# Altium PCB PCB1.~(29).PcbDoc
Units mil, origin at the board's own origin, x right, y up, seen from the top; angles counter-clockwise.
Board outline 5610 x 800 mil, 2 copper layers (Top Layer, Bottom Layer); 100 components, 175 nets, 474 pads, 134 vias.
Unrouted connection lines stored in the file: 2.
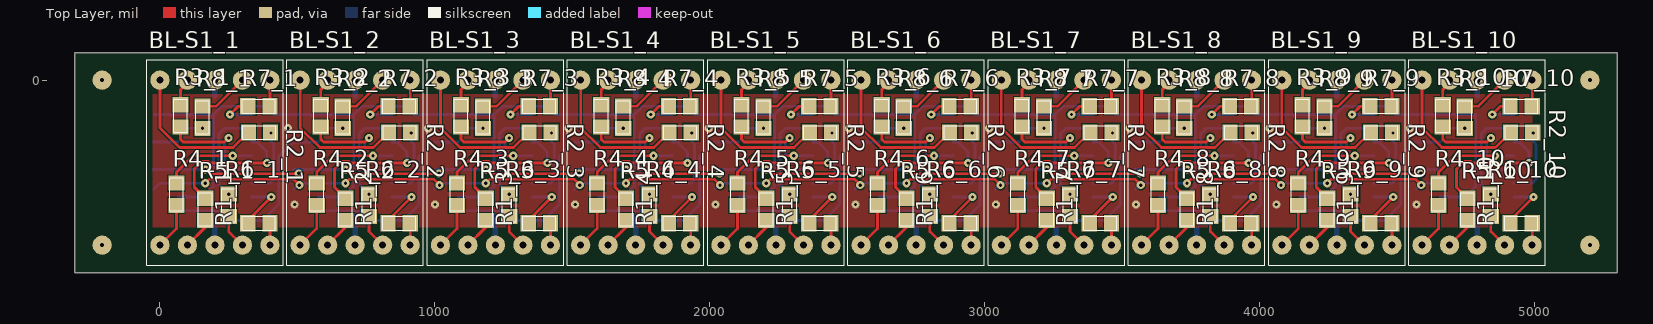
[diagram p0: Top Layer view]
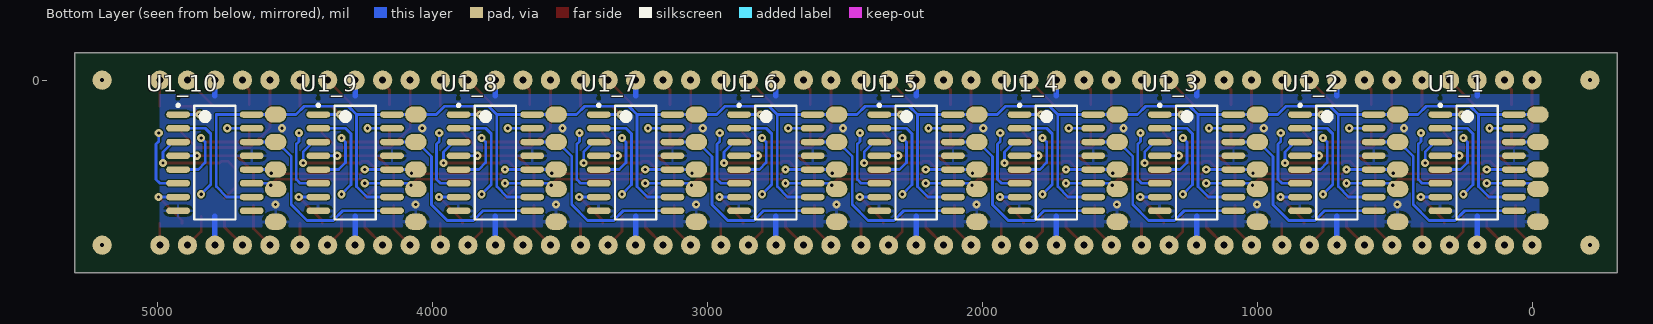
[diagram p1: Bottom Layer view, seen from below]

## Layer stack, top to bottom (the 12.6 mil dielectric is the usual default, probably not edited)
Top Solder: solder mask 0.4, Solder Resist, Dk 3.5
Top Layer: signal copper 1.4
Dielectric 1: dielectric 12.6, FR-4, Dk 4.8
Bottom Layer: signal copper 1.4
Bottom Solder: solder mask 0.4, Solder Resist, Dk 3.5

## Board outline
-310,-700 -310,100 5300,100 5300,-700

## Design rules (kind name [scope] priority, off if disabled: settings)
Clearance [All] p1: gap=5
MinimumSolderMaskSliver [All] p1 off: minsoldermaskwidth=10
PolygonConnect toLEDS [HasFootprint('BL-S56A-11UR')] p1: connectstyle=Relief reliefconductorwidth=10 reliefentries=4 polygonreliefangle="45 Angle" airgapwidth=10
PolygonConnect toPADS [InPadClass('GND_PADS')] p2: connectstyle=Relief reliefconductorwidth=10 reliefentries=4 polygonreliefangle="90 Angle" airgapwidth=10
PolygonConnect toHC74 [HasFootprint('PRSP0016DH-B_N')] p3: connectstyle=Relief reliefconductorwidth=10 reliefentries=4 polygonreliefangle="90 Angle" airgapwidth=10
PolygonConnect [All] p4: connectstyle=Direct reliefconductorwidth=10 reliefentries=4 polygonreliefangle="90 Angle" airgapwidth=15
RoomDefinition 10 [InComponentClass('10')] p1: confinementstyle=ConfineIn formatcopy=TRUE lockcomponents=TRUE outline 4525,-700 4525,100 5042,100 5042,-700
RoomDefinition 9 [InComponentClass('9')] p2: confinementstyle=ConfineIn formatcopy=TRUE lockcomponents=TRUE outline 4015,-700 4015,100 4532,100 4532,-700
RoomDefinition 8 [InComponentClass('8')] p3: confinementstyle=ConfineIn formatcopy=TRUE lockcomponents=TRUE outline 3505,-700 3505,100 4022,100 4022,-700
RoomDefinition 7 [InComponentClass('7')] p4: confinementstyle=ConfineIn formatcopy=TRUE lockcomponents=TRUE outline 2995,-700 2995,100 3512,100 3512,-700
RoomDefinition 6 [InComponentClass('6')] p5: confinementstyle=ConfineIn formatcopy=TRUE lockcomponents=TRUE outline 2485,-700 2485,100 3002,100 3002,-700
RoomDefinition 5 [InComponentClass('5')] p6: confinementstyle=ConfineIn formatcopy=TRUE lockcomponents=TRUE outline 1975,-700 1975,100 2492,100 2492,-700
RoomDefinition 4 [InComponentClass('4')] p7: confinementstyle=ConfineIn formatcopy=TRUE lockcomponents=TRUE outline 1465,-700 1465,100 1982,100 1982,-700
RoomDefinition 2 [InComponentClass('2')] p8: confinementstyle=ConfineIn formatcopy=TRUE lockcomponents=FALSE outline 445,-700 445,100 962,100 962,-700
RoomDefinition 1 [InComponentClass('1')] p9: confinementstyle=ConfineIn formatcopy=TRUE lockcomponents=FALSE outline -65,-700 -65,100 452,100 452,-700
RoomDefinition 3 [InComponentClass('3')] p10: confinementstyle=ConfineIn formatcopy=TRUE lockcomponents=TRUE outline 955,-700 955,100 1472,100 1472,-700
RoutingVias [All] p1: holewidth=11.81 width=29.53 viastyle="Through Hole" minholewidth=11.81 minwidth=29.53 maxholewidth=28 maxwidth=70
SilkToBoardRegionClearance [All] p1 off:
SilkToSilkClearance [All] p1 off: silktosilkclearance=10
SilkToSolderMaskClearance [IsPad] p1 off: minsilkscreentomaskgap=10 clearancetoexposedcopper=TRUE
SolderMaskExpansion [All] p1: expansion=4
Width [All] p1: maxlimit=20 minlimit=7.87 preferedwidth=10
26 further rules are at their usual default settings.

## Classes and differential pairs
pad class GND_PADS: Free-ref
component class 6: BL-S1_6 R1_6 R2_6 R3_6 R4_6 R5_6 R6_6 R7_6 R8_6 U1_6
component class 5: BL-S1_5 R1_5 R2_5 R3_5 R4_5 R5_5 R6_5 R7_5 R8_5 U1_5
component class 1: BL-S1_1 R1_1 R2_1 R3_1 R4_1 R5_1 R6_1 R7_1 R8_1 U1_1
component class 2: R1_2 R2_2 R3_2 R4_2 R5_2 R6_2 R7_2 R8_2 U1_2
component class 3: BL-S1_3 R1_3 R2_3 R3_3 R4_3 R5_3 R6_3 R7_3 R8_3 U1_3
component class 4: BL-S1_4 R1_4 R2_4 R3_4 R4_4 R5_4 R6_4 R7_4 R8_4 U1_4
channel class Sheet2: 1 2 3 4 5 6 7 8 9 10
component class 7: BL-S1_7 R1_7 R2_7 R3_7 R4_7 R5_7 R6_7 R7_7 R8_7 U1_7
component class 8: BL-S1_8 R1_8 R2_8 R3_8 R4_8 R5_8 R6_8 R7_8 R8_8 U1_8
component class 9: BL-S1_9 R1_9 R2_9 R3_9 R4_9 R5_9 R6_9 R7_9 R8_9 U1_9
component class 10: BL-S1_10 R1_10 R2_10 R3_10 R4_10 R5_10 R6_10 R7_10 R8_10 U1_10
net class LEDS: L_A_1 L_A_2 L_A_3 L_A_4 L_A_5 L_A_6 L_A_7 L_A_8 L_A_9 L_A_10 L_B_1 L_B_2 L_B_3 L_B_4 L_B_5 L_B_6 L_B_7 L_B_8 L_B_9 L_B_10 L_C_1 L_C_2 L_C_3 L_C_4 L_C_5 L_C_6 L_C_7 L_C_8 L_C_9 L_C_10 L_D_1 L_D_2 L_D_3 L_D_4 L_D_5 L_D_6 L_D_7 L_D_8 L_D_9 L_D_10 L_E_1 L_E_2 L_E_3 L_E_4 L_E_5 L_E_6 L_E_7 L_E_8 L_E_9 L_E_10 L_F_1 L_F_2 L_F_3 L_F_4 L_F_5 L_F_6 L_F_7 L_F_8 L_F_9 L_F_10 L_G_1 L_G_2 L_G_3 L_G_4 L_G_5 L_G_6 L_G_7 L_G_8 L_G_9 L_G_10 L_H_1 L_H_2 L_H_3 L_H_4 L_H_5 L_H_6 L_H_7 L_H_8 L_H_9 L_H_10

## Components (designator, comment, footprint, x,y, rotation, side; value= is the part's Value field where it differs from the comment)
BL-S1_1 "BL-S56A-11UR" BL-S56A-11UR -48.03,-300 r0 top (schematic designator BL-S1)
BL-S1_2 "BL-S56A-11UR" BL-S56A-11UR 461.97,-300 r0 top (schematic designator BL-S1)
BL-S1_3 "BL-S56A-11UR" BL-S56A-11UR 971.97,-300 r0 top (schematic designator BL-S1)
BL-S1_4 "BL-S56A-11UR" BL-S56A-11UR 1481.97,-300 r0 top (schematic designator BL-S1)
BL-S1_5 "BL-S56A-11UR" BL-S56A-11UR 1991.97,-300 r0 top (schematic designator BL-S1)
BL-S1_6 "BL-S56A-11UR" BL-S56A-11UR 2501.97,-300 r0 top (schematic designator BL-S1)
BL-S1_7 "BL-S56A-11UR" BL-S56A-11UR 3011.97,-300 r0 top (schematic designator BL-S1)
BL-S1_8 "BL-S56A-11UR" BL-S56A-11UR 3521.97,-300 r0 top (schematic designator BL-S1)
BL-S1_9 "BL-S56A-11UR" BL-S56A-11UR 4031.97,-300 r0 top (schematic designator BL-S1)
BL-S1_10 "BL-S56A-11UR" BL-S56A-11UR 4541.97,-300 r0 top (schematic designator BL-S1)
R1_1 "310R" Res0805 360,-520 r180 top (schematic designator R1)
R1_2 "310R" Res0805 870,-520 r180 top (schematic designator R1)
R1_3 "310R" Res0805 1380,-520 r180 top (schematic designator R1)
R1_4 "310R" Res0805 1890,-520 r180 top (schematic designator R1)
R1_5 "310R" Res0805 2400,-520 r180 top (schematic designator R1)
R1_6 "310R" Res0805 2910,-520 r180 top (schematic designator R1)
R1_7 "310R" Res0805 3420,-520 r180 top (schematic designator R1)
R1_8 "310R" Res0805 3930,-520 r180 top (schematic designator R1)
R1_9 "310R" Res0805 4440,-520 r180 top (schematic designator R1)
R1_10 "310R" Res0805 4950,-520 r180 top (schematic designator R1)
R2_1 "310R" Res0805 362.05,-190 r0 top (schematic designator R2)
R2_2 "310R" Res0805 872.05,-190 r0 top (schematic designator R2)
R2_3 "310R" Res0805 1382.05,-190 r0 top (schematic designator R2)
R2_4 "310R" Res0805 1892.05,-190 r0 top (schematic designator R2)
R2_5 "310R" Res0805 2402.05,-190 r0 top (schematic designator R2)
R2_6 "310R" Res0805 2912.05,-190 r0 top (schematic designator R2)
R2_7 "310R" Res0805 3422.05,-190 r0 top (schematic designator R2)
R2_8 "310R" Res0805 3932.05,-190 r0 top (schematic designator R2)
R2_9 "310R" Res0805 4442.05,-190 r0 top (schematic designator R2)
R2_10 "310R" Res0805 4952.05,-190 r0 top (schematic designator R2)
R3_1 "310R" Res0805 75,-130 r270 top (schematic designator R3)
R3_2 "310R" Res0805 585,-130 r270 top (schematic designator R3)
R3_3 "310R" Res0805 1095,-130 r270 top (schematic designator R3)
R3_4 "310R" Res0805 1605,-130 r270 top (schematic designator R3)
R3_5 "310R" Res0805 2115,-130 r270 top (schematic designator R3)
R3_6 "310R" Res0805 2625,-130 r270 top (schematic designator R3)
R3_7 "310R" Res0805 3135,-130 r270 top (schematic designator R3)
R3_8 "310R" Res0805 3645,-130 r270 top (schematic designator R3)
R3_9 "310R" Res0805 4155,-130 r270 top (schematic designator R3)
R3_10 "310R" Res0805 4665,-130 r270 top (schematic designator R3)
R4_1 "310R" Res0805 60,-415 r90 top (schematic designator R4)
R4_2 "310R" Res0805 570,-415 r90 top (schematic designator R4)
R4_3 "310R" Res0805 1080,-415 r90 top (schematic designator R4)
R4_4 "310R" Res0805 1590,-415 r90 top (schematic designator R4)
R4_5 "310R" Res0805 2100,-415 r90 top (schematic designator R4)
R4_6 "310R" Res0805 2610,-415 r90 top (schematic designator R4)
R4_7 "310R" Res0805 3120,-415 r90 top (schematic designator R4)
R4_8 "310R" Res0805 3630,-415 r90 top (schematic designator R4)
R4_9 "310R" Res0805 4140,-415 r90 top (schematic designator R4)
R4_10 "310R" Res0805 4650,-415 r90 top (schematic designator R4)
R5_1 "310R" Res0805 165,-470 r90 top (schematic designator R5)
R5_2 "310R" Res0805 675,-470 r90 top (schematic designator R5)
R5_3 "310R" Res0805 1185,-470 r90 top (schematic designator R5)
R5_4 "310R" Res0805 1695,-470 r90 top (schematic designator R5)
R5_5 "310R" Res0805 2205,-470 r90 top (schematic designator R5)
R5_6 "310R" Res0805 2715,-470 r90 top (schematic designator R5)
R5_7 "310R" Res0805 3225,-470 r90 top (schematic designator R5)
R5_8 "310R" Res0805 3735,-470 r90 top (schematic designator R5)
R5_9 "310R" Res0805 4245,-470 r90 top (schematic designator R5)
R5_10 "310R" Res0805 4755,-470 r90 top (schematic designator R5)
R6_1 "310R" Res0805 250,-455 r90 top (schematic designator R6)
R6_2 "310R" Res0805 760,-455 r90 top (schematic designator R6)
R6_3 "310R" Res0805 1270,-455 r90 top (schematic designator R6)
R6_4 "310R" Res0805 1780,-455 r90 top (schematic designator R6)
R6_5 "310R" Res0805 2290,-455 r90 top (schematic designator R6)
R6_6 "310R" Res0805 2800,-455 r90 top (schematic designator R6)
R6_7 "310R" Res0805 3310,-455 r90 top (schematic designator R6)
R6_8 "310R" Res0805 3820,-455 r90 top (schematic designator R6)
R6_9 "310R" Res0805 4330,-455 r90 top (schematic designator R6)
R6_10 "310R" Res0805 4840,-455 r90 top (schematic designator R6)
R7_1 "310R" Res0805 360,-95 r180 top (schematic designator R7)
R7_2 "310R" Res0805 870,-95 r180 top (schematic designator R7)
R7_3 "310R" Res0805 1380,-95 r180 top (schematic designator R7)
R7_4 "310R" Res0805 1890,-95 r180 top (schematic designator R7)
R7_5 "310R" Res0805 2400,-95 r180 top (schematic designator R7)
R7_6 "310R" Res0805 2910,-95 r180 top (schematic designator R7)
R7_7 "310R" Res0805 3420,-95 r180 top (schematic designator R7)
R7_8 "310R" Res0805 3930,-95 r180 top (schematic designator R7)
R7_9 "310R" Res0805 4440,-95 r180 top (schematic designator R7)
R7_10 "310R" Res0805 4950,-95 r180 top (schematic designator R7)
R8_1 "310R" Res0805 155,-135 r270 top (schematic designator R8)
R8_2 "310R" Res0805 665,-135 r270 top (schematic designator R8)
R8_3 "310R" Res0805 1175,-135 r270 top (schematic designator R8)
R8_4 "310R" Res0805 1685,-135 r270 top (schematic designator R8)
R8_5 "310R" Res0805 2195,-135 r270 top (schematic designator R8)
R8_6 "310R" Res0805 2705,-135 r270 top (schematic designator R8)
R8_7 "310R" Res0805 3215,-135 r270 top (schematic designator R8)
R8_8 "310R" Res0805 3725,-135 r270 top (schematic designator R8)
R8_9 "310R" Res0805 4235,-135 r270 top (schematic designator R8)
R8_10 "310R" Res0805 4745,-135 r270 top (schematic designator R8)
U1_1 "HD74HC595FP" PRSP0016DH-B_N 200,-300 r180 bottom (schematic designator U1)
U1_2 "HD74HC595FP" PRSP0016DH-B_N 710,-300 r180 bottom (schematic designator U1)
U1_3 "HD74HC595FP" PRSP0016DH-B_N 1220,-300 r180 bottom (schematic designator U1)
U1_4 "HD74HC595FP" PRSP0016DH-B_N 1730,-300 r180 bottom (schematic designator U1)
U1_5 "HD74HC595FP" PRSP0016DH-B_N 2240,-300 r180 bottom (schematic designator U1)
U1_6 "HD74HC595FP" PRSP0016DH-B_N 2750,-300 r180 bottom (schematic designator U1)
U1_7 "HD74HC595FP" PRSP0016DH-B_N 3260,-300 r180 bottom (schematic designator U1)
U1_8 "HD74HC595FP" PRSP0016DH-B_N 3770,-300 r180 bottom (schematic designator U1)
U1_9 "HD74HC595FP" PRSP0016DH-B_N 4280,-300 r180 bottom (schematic designator U1)
U1_10 "HD74HC595FP" PRSP0016DH-B_N 4790,-300 r180 bottom (schematic designator U1)

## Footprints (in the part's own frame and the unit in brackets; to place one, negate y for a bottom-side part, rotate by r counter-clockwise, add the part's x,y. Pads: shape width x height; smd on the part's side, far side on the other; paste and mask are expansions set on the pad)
BL-S56A-11UR [mil]
  round 70 hole 25.59: 1(48.03,-300) 2(148.03,-300) 3(248.03,-300) 4(348.03,-300) 5(448.03,-300) 6(448.03,300) 7(348.03,300) 8(248.03,300) 9(148.03,300) 10(48.03,300)
  silkscreen extent 0,-374 496,374
PRSP0016DH-B_N [mm] "SOP, 16-Leads, Body 10.06x5.5mm, Pitch 1.27mm, IPC Medium Density"
  oval 2.2x0.6 smd: 1(-3.4,4.445) 2(-3.4,3.175) 3(-3.4,1.905) 4(-3.4,0.635) 5(-3.4,-0.635) 6(-3.4,-1.905) 7(-3.4,-3.175) 8(-3.4,-4.445) 9(3.4,-4.445) 10(3.4,-3.175) 11(3.4,-1.905) 12(3.4,-0.635) 13(3.4,0.635) 14(3.4,1.905) 15(3.4,3.175) 16(3.4,4.445)
  silkscreen extent -3.52,-5.25 1.9,5.42, body extent -2.7,-5.25 2.7,5.25, height 2.2
Res0805 [mm]
  rect 1.4x1.5 smd: 1(-1.025,0) 2(1.025,0)
  silkscreen extent -1.52,-0.64 1.52,0.64, body extent -1.15,-0.67 1.15,0.68, height 0.76

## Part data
BL-S1_1 BL-S1_2 BL-S1_3 BL-S1_4 BL-S1_5 BL-S1_6 BL-S1_7 BL-S1_8 BL-S1_9 BL-S1_10: library part Component_1
R1_1 R1_2 R1_3 R1_4 R1_5 R1_6 R1_7 R1_8 R1_9 R1_10 R2_1 R2_2 R2_3 R2_4 R2_5 R2_6 R2_7 R2_8 R2_9 R2_10 R3_1 R3_2 R3_3 R3_4 R3_5 R3_6 R3_7 R3_8 R3_9 R3_10 R4_1 R4_2 R4_3 R4_4 R4_5 R4_6 R4_7 R4_8 R4_9 R4_10 R5_1 R5_2 R5_3 R5_4 R5_5 R5_6 R5_7 R5_8 R5_9 R5_10 R6_1 R6_2 R6_3 R6_4 R6_5 R6_6 R6_7 R6_8 R6_9 R6_10 R7_1 R7_2 R7_3 R7_4 R7_5 R7_6 R7_7 R7_8 R7_9 R7_10 R8_1 R8_2 R8_3 R8_4 R8_5 R8_6 R8_7 R8_8 R8_9 R8_10: library part Res1, "Resistor"
U1_1 U1_2 U1_3 U1_4 U1_5 U1_6 U1_7 U1_8 U1_9 U1_10: "8-bit Shift Register / Latch with 3-State Outputs"

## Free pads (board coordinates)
  oval 78.74x59.06 smd far side: 8(-20.94,-125) 8(489.06,-125) 8(999.06,-125) 8(1509.06,-125) 8(2019.06,-125) 8(2529.06,-125) 8(3039.06,-125) 8(3549.06,-125) 8(4059.06,-125) 8(4569.06,-125) 9(-20.94,-225) 9(489.06,-225) 9(999.06,-225) 9(1509.06,-225) 9(2019.06,-225) 9(2529.06,-225) 9(3039.06,-225) 9(3549.06,-225) 9(4059.06,-225) 9(4569.06,-225) 10(-20.94,-325) 10(489.06,-325) 10(999.06,-325) 10(1509.06,-325) 10(2019.06,-325) 10(2529.06,-325) 10(3039.06,-325) 10(3549.06,-325) 10(4059.06,-325) 10(4569.06,-325) 11(-21,-396) 11(489,-396) 11(999,-396) 11(1509,-396) 11(2019,-396) 11(2529,-396) 11(3039,-396) 11(3549,-396) 11(4059,-396) 11(4569,-396) ref(-21,-515) ref(489,-515) ref(999,-515) ref(1509,-515) ref(2019,-515) ref(2529,-515) ref(3039,-515) ref(3549,-515) ref(4059,-515) ref(4569,-515)
  round 70 hole 15: 12(-210,-600) 12(-210,0) 12(5200,-600) 12(5200,0)

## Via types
v1: diameter 29.53, hole 11.81, Top Layer to Bottom Layer, tented both sides, 78 vias
v2: diameter 29.53, hole 11.81, Top Layer to Bottom Layer, tented top, 36 vias
v3: diameter 29.53, hole 11.81, Top Layer to Bottom Layer, 20 vias

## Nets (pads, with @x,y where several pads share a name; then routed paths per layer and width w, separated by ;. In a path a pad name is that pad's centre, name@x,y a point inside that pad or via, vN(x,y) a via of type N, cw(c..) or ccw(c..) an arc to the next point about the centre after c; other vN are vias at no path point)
+5V: pad.8 U1_1.10 U1_1.16 U1_2.10 U1_2.16 U1_3.10 U1_3.16 U1_4.10 U1_4.16 U1_5.10 U1_5.16 U1_6.10 U1_6.16 U1_7.10 U1_7.16 U1_8.10 U1_8.16 U1_9.10 U1_9.16 U1_10.10 U1_10.16 | length 9617.7
  Bottom Layer w10: pad.8@-20.94,-125 U1_1.16 195,-125 225,-95 385,-95 415,-125 U1_2.16 ; U1_1.10 157.09,-425 194.76,-387.33 194.76,-125 ; pad.8@489.06,-125 U1_2.16 ; U1_2.10 667.09,-425 704.76,-387.33 704.76,-125 ; U1_3.10 1177.09,-425 1214.76,-387.33 1214.76,-125 ; U1_4.10 1687.09,-425 1724.76,-387.33 1724.76,-125 ; U1_5.10 2197.09,-425 2234.76,-387.33 2234.76,-125 ; pad.8@2529.06,-125 2745,-125 2775,-95 2935,-95 2965,-125 U1_7.16 ; U1_6.10 2707.09,-425 2744.76,-387.33 2744.76,-125 ; U1_6.16 2455,-125 2425,-95 2265,-95 2235,-125 2019.06,-125 1945,-125 1915,-95 1755,-95 1725,-125 U1_4.16 1509.06,-125 1435,-125 1405,-95 1245,-95 1215,-125 U1_3.16 999.06,-125 925,-125 895,-95 735,-95 705,-125 U1_2.16 ; pad.8@3039.06,-125 3255,-125 3285,-95 3445,-95 3475,-125 U1_8.16 ; U1_7.10 3217.09,-425 3254.76,-387.33 3254.76,-125 ; pad.8@3549.06,-125 3765,-125 3795,-95 3955,-95 3985,-125 U1_9.16 ; U1_8.10 3727.09,-425 3764.76,-387.33 3764.76,-125 ; pad.8@4059.06,-125 4275,-125 4305,-95 4465,-95 4495,-125 U1_10.16 ; U1_9.10 4237.09,-425 4274.76,-387.33 4274.76,-125 ; pad.8@4569.06,-125 4785,-125 ; U1_10.10 4747.09,-425 4784.76,-387.33 4784.76,-125
GND: BL-S1_1.3 BL-S1_1.8 BL-S1_2.3 BL-S1_2.8 BL-S1_3.3 BL-S1_3.8 BL-S1_4.3 BL-S1_4.8 BL-S1_5.3 BL-S1_5.8 BL-S1_6.3 BL-S1_6.8 BL-S1_7.3 BL-S1_7.8 BL-S1_8.3 BL-S1_8.8 BL-S1_9.3 BL-S1_9.8 BL-S1_10.3 BL-S1_10.8 pad.ref U1_1.8 U1_1.13 U1_2.8 U1_2.13 U1_3.8 U1_3.13 U1_4.8 U1_4.13 U1_5.8 U1_5.13 U1_6.8 U1_6.13 U1_7.8 U1_7.13 U1_8.8 U1_8.13 U1_9.8 U1_9.13 U1_10.8 U1_10.13 | length 1611.4
  Bottom Layer w10: 199,-57 200,-56
  Bottom Layer w20: BL-S1_1.3 200,-495 ; 200,-56 BL-S1_1.8 ; BL-S1_2.3 710,-495 ; 710,-56 BL-S1_2.8 ; BL-S1_3.3 1220,-495 ; 1220,-56 BL-S1_3.8 ; BL-S1_4.3 1730,-495 ; 1730,-56 BL-S1_4.8 ; BL-S1_5.3 2240,-495 ; 2240,-56 BL-S1_5.8 ; BL-S1_6.3 2750,-495 ; 2750,-56 BL-S1_6.8 ; BL-S1_7.3 3260,-495 ; 3260,-56 BL-S1_7.8 ; BL-S1_8.3 3770,-495 ; 3770,-56 BL-S1_8.8 ; BL-S1_9.3 4280,-495 ; 4280,-56 BL-S1_9.8 ; BL-S1_10.3 4790,-495 ; 4790,-56 BL-S1_10.8
  other v1: 490,-452 1000,-452 1510,-452 2020,-452 2530,-452 3040,-452 3550,-452 4060,-452 4570,-452 466,-175 976,-175 1486,-175 1996,-175 2506,-175 3016,-175 3526,-175 4036,-175 4546,-175
L_A_1: BL-S1_1.7 R8_1.1 | length 184.2
  Top Layer w10: R8_1.1 205.35,-94.65 BL-S1_1.7
L_A_2: BL-S1_2.7 R8_2.1 | length 184.2
  Top Layer w10: R8_2.1 715.35,-94.65 BL-S1_2.7
L_A_3: BL-S1_3.7 R8_3.1 | length 184.2
  Top Layer w10: R8_3.1 1225.35,-94.65 BL-S1_3.7
L_A_4: BL-S1_4.7 R8_4.1 | length 184.2
  Top Layer w10: R8_4.1 1735.35,-94.65 BL-S1_4.7
L_A_5: BL-S1_5.7 R8_5.1 | length 184.2
  Top Layer w10: R8_5.1 2245.36,-94.64 BL-S1_5.7
L_A_6: BL-S1_6.7 R8_6.1 | length 184.2
  Top Layer w10: R8_6.1 2755.36,-94.64 BL-S1_6.7
L_A_7: BL-S1_7.7 R8_7.1 | length 184.2
  Top Layer w10: R8_7.1 3265.36,-94.64 BL-S1_7.7
L_A_8: BL-S1_8.7 R8_8.1 | length 184.2
  Top Layer w10: R8_8.1 3775.36,-94.64 BL-S1_8.7
L_A_9: BL-S1_9.7 R8_9.1 | length 184.2
  Top Layer w10: R8_9.1 4285.36,-94.64 BL-S1_9.7
L_A_10: BL-S1_10.7 R8_10.1 | length 184.2
  Top Layer w10: R8_10.1 4795.36,-94.64 BL-S1_10.7
L_B_1: BL-S1_1.6 R7_1.1 | length 95.1
  Top Layer w10: BL-S1_1.6 400.35,-0.35 R7_1.1
L_B_2: BL-S1_2.6 R7_2.1 | length 95.1
  Top Layer w10: BL-S1_2.6 910.35,-0.35 R7_2.1
L_B_3: BL-S1_3.6 R7_3.1 | length 95.1
  Top Layer w10: BL-S1_3.6 1420.35,-0.35 R7_3.1
L_B_4: BL-S1_4.6 R7_4.1 | length 95.1
  Top Layer w10: BL-S1_4.6 1930.35,-0.35 R7_4.1
L_B_5: BL-S1_5.6 R7_5.1 | length 95.1
  Top Layer w10: BL-S1_5.6 2440.35,-0.35 R7_5.1
L_B_6: BL-S1_6.6 R7_6.1 | length 95.1
  Top Layer w10: BL-S1_6.6 2950.35,-0.35 R7_6.1
L_B_7: BL-S1_7.6 R7_7.1 | length 95.1
  Top Layer w10: BL-S1_7.6 3460.35,-0.35 R7_7.1
L_B_8: BL-S1_8.6 R7_8.1 | length 95.1
  Top Layer w10: BL-S1_8.6 3970.35,-0.35 R7_8.1
L_B_9: BL-S1_9.6 R7_9.1 | length 95.1
  Top Layer w10: BL-S1_9.6 4480.35,-0.35 R7_9.1
L_B_10: BL-S1_10.6 R7_10.1 | length 95.1
  Top Layer w10: BL-S1_10.6 4990.35,-0.35 R7_10.1
L_C_1: BL-S1_1.4 R6_1.1 | length 125.4
  Top Layer w10: R6_1.1 250,-550 BL-S1_1.4
L_C_2: BL-S1_2.4 R6_2.1 | length 125.4
  Top Layer w10: R6_2.1 760,-550 BL-S1_2.4
L_C_3: BL-S1_3.4 R6_3.1 | length 125.4
  Top Layer w10: R6_3.1 1270,-550 BL-S1_3.4
L_C_4: BL-S1_4.4 R6_4.1 | length 125.4
  Top Layer w10: R6_4.1 1780,-550 BL-S1_4.4
L_C_5: BL-S1_5.4 R6_5.1 | length 125.4
  Top Layer w10: R6_5.1 2290,-550 BL-S1_5.4
L_C_6: BL-S1_6.4 R6_6.1 | length 125.4
  Top Layer w10: R6_6.1 2800,-550 BL-S1_6.4
L_C_7: BL-S1_7.4 R6_7.1 | length 125.4
  Top Layer w10: R6_7.1 3310,-550 BL-S1_7.4
L_C_8: BL-S1_8.4 R6_8.1 | length 125.4
  Top Layer w10: R6_8.1 3820,-550 BL-S1_8.4
L_C_9: BL-S1_9.4 R6_9.1 | length 125.4
  Top Layer w10: R6_9.1 4330,-550 BL-S1_9.4
L_C_10: BL-S1_10.4 R6_10.1 | length 125.4
  Top Layer w10: R6_10.1 4840,-550 BL-S1_10.4
L_D_1: BL-S1_1.2 R5_1.1 | length 111.6
  Top Layer w10: BL-S1_1.2 165,-535 R5_1.1@165,-515.35
L_D_2: BL-S1_2.2 R5_2.1 | length 111.6
  Top Layer w10: BL-S1_2.2 675,-535 R5_2.1@675,-515.35
L_D_3: BL-S1_3.2 R5_3.1 | length 111.6
  Top Layer w10: BL-S1_3.2 1185,-535 R5_3.1@1185,-515.35
L_D_4: BL-S1_4.2 R5_4.1 | length 111.6
  Top Layer w10: BL-S1_4.2 1695,-535 R5_4.1@1695,-515.35
L_D_5: BL-S1_5.2 R5_5.1 | length 111.6
  Top Layer w10: BL-S1_5.2 2205,-535 R5_5.1@2205,-515.35
L_D_6: BL-S1_6.2 R5_6.1 | length 111.6
  Top Layer w10: BL-S1_6.2 2715,-535 R5_6.1@2715,-515.35
L_D_7: BL-S1_7.2 R5_7.1 | length 111.6
  Top Layer w10: BL-S1_7.2 3225,-535 R5_7.1@3225,-515.35
L_D_8: BL-S1_8.2 R5_8.1 | length 111.6
  Top Layer w10: BL-S1_8.2 3735,-535 R5_8.1@3735,-515.35
L_D_9: BL-S1_9.2 R5_9.1 | length 111.6
  Top Layer w10: BL-S1_9.2 4245,-535 R5_9.1@4245,-515.35
L_D_10: BL-S1_10.2 R5_10.1 | length 111.6
  Top Layer w10: BL-S1_10.2 4755,-535 R5_10.1@4755,-515.35
L_E_1: BL-S1_1.1 R4_1.1 | length 169.5
  Top Layer w10: BL-S1_1.1 60,-540 R4_1.1
L_E_2: BL-S1_2.1 R4_2.1 | length 169.5
  Top Layer w10: BL-S1_2.1 570,-540 R4_2.1
L_E_3: BL-S1_3.1 R4_3.1 | length 169.5
  Top Layer w10: BL-S1_3.1 1080,-540 R4_3.1
L_E_4: BL-S1_4.1 R4_4.1 | length 169.5
  Top Layer w10: BL-S1_4.1 1590,-540 R4_4.1
L_E_5: BL-S1_5.1 R4_5.1 | length 169.5
  Top Layer w10: BL-S1_5.1 2100,-540 R4_5.1
L_E_6: BL-S1_6.1 R4_6.1 | length 169.5
  Top Layer w10: BL-S1_6.1 2610,-540 R4_6.1
L_E_7: BL-S1_7.1 R4_7.1 | length 169.5
  Top Layer w10: BL-S1_7.1 3120,-540 R4_7.1
L_E_8: BL-S1_8.1 R4_8.1 | length 169.5
  Top Layer w10: BL-S1_8.1 3630,-540 R4_8.1
L_E_9: BL-S1_9.1 R4_9.1 | length 169.5
  Top Layer w10: BL-S1_9.1 4140,-540 R4_9.1
L_E_10: BL-S1_10.1 R4_10.1 | length 169.5
  Top Layer w10: BL-S1_10.1 4650,-540 R4_10.1
L_F_1: BL-S1_1.9 R3_1.1 | length 100
  Top Layer w10: R3_1.1 75,-35 100,-10 BL-S1_1.9
L_F_2: BL-S1_2.9 R3_2.1 | length 100
  Top Layer w10: R3_2.1 585,-35 610,-10 BL-S1_2.9
L_F_3: BL-S1_3.9 R3_3.1 | length 100
  Top Layer w10: R3_3.1 1095,-35 1120,-10 BL-S1_3.9
L_F_4: BL-S1_4.9 R3_4.1 | length 100
  Top Layer w10: R3_4.1 1605,-35 1630,-10 BL-S1_4.9
L_F_5: BL-S1_5.9 R3_5.1 | length 100
  Top Layer w10: R3_5.1 2115,-35 2140,-10 BL-S1_5.9
L_F_6: BL-S1_6.9 R3_6.1 | length 100
  Top Layer w10: R3_6.1 2625,-35 2650,-10 BL-S1_6.9
L_F_7: BL-S1_7.9 R3_7.1 | length 100
  Top Layer w10: R3_7.1 3135,-35 3160,-10 BL-S1_7.9
L_F_8: BL-S1_8.9 R3_8.1 | length 100
  Top Layer w10: R3_8.1 3645,-35 3670,-10 BL-S1_8.9
L_F_9: BL-S1_9.9 R3_9.1 | length 100
  Top Layer w10: R3_9.1 4155,-35 4180,-10 BL-S1_9.9
L_F_10: BL-S1_10.9 R3_10.1 | length 100
  Top Layer w10: R3_10.1 4665,-35 4690,-10 BL-S1_10.9
L_G_1: BL-S1_1.10 R2_1.1 | length 547.9
  Top Layer w10: BL-S1_1.10 0,-173.65 71.58,-245.24 266.46,-245.24 R2_1.1
L_G_2: BL-S1_2.10 R2_2.1 | length 547.9
  Top Layer w10: BL-S1_2.10 510,-173.65 581.58,-245.24 776.46,-245.24 R2_2.1
L_G_3: BL-S1_3.10 R2_3.1 | length 547.9
  Top Layer w10: BL-S1_3.10 1020,-173.65 1091.58,-245.24 1286.46,-245.24 R2_3.1
L_G_4: BL-S1_4.10 R2_4.1 | length 547.9
  Top Layer w10: BL-S1_4.10 1530,-173.65 1601.58,-245.24 1796.46,-245.24 R2_4.1
L_G_5: BL-S1_5.10 R2_5.1 | length 547.9
  Top Layer w10: BL-S1_5.10 2040,-173.65 2111.58,-245.24 2306.46,-245.24 R2_5.1
L_G_6: BL-S1_6.10 R2_6.1 | length 547.9
  Top Layer w10: BL-S1_6.10 2550,-173.65 2621.58,-245.24 2816.46,-245.24 R2_6.1
L_G_7: BL-S1_7.10 R2_7.1 | length 547.9
  Top Layer w10: BL-S1_7.10 3060,-173.65 3131.58,-245.24 3326.46,-245.24 R2_7.1
L_G_8: BL-S1_8.10 R2_8.1 | length 547.9
  Top Layer w10: BL-S1_8.10 3570,-173.65 3641.58,-245.24 3836.46,-245.24 R2_8.1
L_G_9: BL-S1_9.10 R2_9.1 | length 547.9
  Top Layer w10: BL-S1_9.10 4080,-173.65 4151.58,-245.24 4346.46,-245.24 R2_9.1
L_G_10: BL-S1_10.10 R2_10.1 | length 547.9
  Top Layer w10: BL-S1_10.10 4590,-173.65 4661.58,-245.24 4856.46,-245.24 R2_10.1
L_H_1: BL-S1_1.5 R1_1.1 | length 80.1
  Top Layer w10: BL-S1_1.5 400.35,-599.65 R1_1.1
L_H_2: BL-S1_2.5 R1_2.1 | length 80.1
  Top Layer w10: BL-S1_2.5 910.35,-599.65 R1_2.1
L_H_3: BL-S1_3.5 R1_3.1 | length 80.1
  Top Layer w10: BL-S1_3.5 1420.35,-599.65 R1_3.1
L_H_4: BL-S1_4.5 R1_4.1 | length 80.1
  Top Layer w10: BL-S1_4.5 1930.35,-599.65 R1_4.1
L_H_5: BL-S1_5.5 R1_5.1 | length 80.1
  Top Layer w10: BL-S1_5.5 2440.35,-599.65 R1_5.1
L_H_6: BL-S1_6.5 R1_6.1 | length 80.1
  Top Layer w10: BL-S1_6.5 2950.35,-599.65 R1_6.1
L_H_7: BL-S1_7.5 R1_7.1 | length 80.1
  Top Layer w10: BL-S1_7.5 3460.35,-599.65 R1_7.1
L_H_8: BL-S1_8.5 R1_8.1 | length 80.1
  Top Layer w10: BL-S1_8.5 3970.35,-599.65 R1_8.1
L_H_9: BL-S1_9.5 R1_9.1 | length 80.1
  Top Layer w10: BL-S1_9.5 4480.35,-599.65 R1_9.1
L_H_10: BL-S1_10.5 R1_10.1 | length 80.1
  Top Layer w10: BL-S1_10.5 4990.35,-599.65 R1_10.1
NetR1_1_2: R1_1.2 U1_1.7 | length 201.5
  Top Layer w10: R1_1.2 319.65,-510.35 v1(405,-425)
  Bottom Layer w10: U1_1.7 v1(405,-425)
NetR1_2_2: R1_2.2 U1_2.7 | length 201.5
  Top Layer w10: R1_2.2 829.65,-510.35 v1(915,-425)
  Bottom Layer w10: U1_2.7 v1(915,-425)
NetR1_3_2: R1_3.2 U1_3.7 | length 201.5
  Top Layer w10: R1_3.2 1339.65,-510.35 v1(1425,-425)
  Bottom Layer w10: U1_3.7 v1(1425,-425)
NetR1_4_2: R1_4.2 U1_4.7 | length 201.5
  Top Layer w10: R1_4.2 1849.65,-510.35 v1(1935,-425)
  Bottom Layer w10: U1_4.7 v1(1935,-425)
NetR1_5_2: R1_5.2 U1_5.7 | length 201.5
  Top Layer w10: R1_5.2 2359.65,-510.35 v1(2445,-425)
  Bottom Layer w10: U1_5.7 v1(2445,-425)
NetR1_6_2: R1_6.2 U1_6.7 | length 201.5
  Top Layer w10: R1_6.2 2869.65,-510.35 v1(2955,-425)
  Bottom Layer w10: U1_6.7 v1(2955,-425)
NetR1_7_2: R1_7.2 U1_7.7 | length 201.5
  Top Layer w10: R1_7.2 3379.65,-510.35 v1(3465,-425)
  Bottom Layer w10: U1_7.7 v1(3465,-425)
NetR1_8_2: R1_8.2 U1_8.7 | length 201.5
  Top Layer w10: R1_8.2 3889.65,-510.35 v1(3975,-425)
  Bottom Layer w10: U1_8.7 v1(3975,-425)
NetR1_9_2: R1_9.2 U1_9.7 | length 201.5
  Top Layer w10: R1_9.2 4399.65,-510.35 v1(4485,-425)
  Bottom Layer w10: U1_9.7 v1(4485,-425)
NetR1_10_2: R1_10.2 U1_10.7 | length 201.5
  Top Layer w10: R1_10.2 4909.65,-510.35 v1(4995,-425)
  Bottom Layer w10: U1_10.7 v1(4995,-425)
NetR2_1_2: R2_1.2 U1_1.6 | length 258.9
  Bottom Layer w10: U1_1.6 400,-375 413.76,-361.24 413.76,-232.55 404,-222.79 v1(404,-192)
NetR2_2_2: R2_2.2 U1_2.6 | length 258.9
  Bottom Layer w10: U1_2.6 910,-375 923.76,-361.24 923.76,-232.55 914,-222.79 v1(914,-192)
NetR2_3_2: R2_3.2 U1_3.6 | length 258.9
  Bottom Layer w10: U1_3.6 1420,-375 1433.76,-361.24 1433.76,-232.55 1424,-222.79 v1(1424,-192)
NetR2_4_2: R2_4.2 U1_4.6 | length 258.9
  Bottom Layer w10: U1_4.6 1930,-375 1943.76,-361.24 1943.76,-232.55 1934,-222.79 v1(1934,-192)
NetR2_5_2: R2_5.2 U1_5.6 | length 258.9
  Bottom Layer w10: U1_5.6 2440,-375 2453.76,-361.23 2453.76,-232.55 2444,-222.79 v1(2444,-192)
NetR2_6_2: R2_6.2 U1_6.6 | length 258.9
  Bottom Layer w10: U1_6.6 2950,-375 2963.76,-361.23 2963.76,-232.55 2954,-222.79 v1(2954,-192)
NetR2_7_2: R2_7.2 U1_7.6 | length 258.9
  Bottom Layer w10: U1_7.6 3460,-375 3473.76,-361.23 3473.76,-232.55 3464,-222.79 v1(3464,-192)
NetR2_8_2: R2_8.2 U1_8.6 | length 258.9
  Bottom Layer w10: U1_8.6 3970,-375 3983.76,-361.23 3983.76,-232.55 3974,-222.79 v1(3974,-192)
NetR2_9_2: R2_9.2 U1_9.6 | length 258.9
  Bottom Layer w10: U1_9.6 4480,-375 4493.76,-361.23 4493.76,-232.55 4484,-222.79 v1(4484,-192)
NetR2_10_2: R2_10.2 U1_10.6 | length 258.9
  Bottom Layer w10: U1_10.6 4990,-375 5003.76,-361.23 5003.76,-232.55 4994,-222.79 v1(4994,-192)
NetR3_1_2: R3_1.2 U1_1.5 | length 435.2
  Top Layer w10: R3_1.2 75,-215 85,-225 235,-225 v1(250,-210)
  Bottom Layer w10: v1(250,-210) 235.24,-224.76 235.24,-300.24 260,-325 U1_1.5
NetR3_2_2: R3_2.2 U1_2.5 | length 435.2
  Top Layer w10: R3_2.2 585,-215 595,-225 745,-225 v1(760,-210)
  Bottom Layer w10: v1(760,-210) 745.24,-224.76 745.24,-300.24 770,-325 U1_2.5
NetR3_3_2: R3_3.2 U1_3.5 | length 435.2
  Top Layer w10: R3_3.2 1095,-215 1105,-225 1255,-225 v1(1270,-210)
  Bottom Layer w10: v1(1270,-210) 1255.24,-224.76 1255.24,-300.24 1280,-325 U1_3.5
NetR3_4_2: R3_4.2 U1_4.5 | length 435.2
  Top Layer w10: R3_4.2 1605,-215 1615,-225 1765,-225 v1(1780,-210)
  Bottom Layer w10: v1(1780,-210) 1765.24,-224.76 1765.24,-300.24 1790,-325 U1_4.5
NetR3_5_2: R3_5.2 U1_5.5 | length 435.2
  Top Layer w10: R3_5.2 2115,-215 2125,-225 2275,-225 v1(2290,-210)
  Bottom Layer w10: v1(2290,-210) 2275.24,-224.76 2275.24,-300.24 2300,-325 U1_5.5
NetR3_6_2: R3_6.2 U1_6.5 | length 435.2
  Top Layer w10: R3_6.2 2625,-215 2635,-225 2785,-225 v1(2800,-210)
  Bottom Layer w10: v1(2800,-210) 2785.24,-224.76 2785.24,-300.24 2810,-325 U1_6.5
NetR3_7_2: R3_7.2 U1_7.5 | length 435.2
  Top Layer w10: R3_7.2 3135,-215 3145,-225 3295,-225 v1(3310,-210)
  Bottom Layer w10: v1(3310,-210) 3295.24,-224.76 3295.24,-300.24 3320,-325 U1_7.5
NetR3_8_2: R3_8.2 U1_8.5 | length 435.2
  Top Layer w10: R3_8.2 3645,-215 3655,-225 3805,-225 v1(3820,-210)
  Bottom Layer w10: v1(3820,-210) 3805.24,-224.76 3805.24,-300.24 3830,-325 U1_8.5
NetR3_9_2: R3_9.2 U1_9.5 | length 435.2
  Top Layer w10: R3_9.2 4155,-215 4165,-225 4315,-225 v1(4330,-210)
  Bottom Layer w10: v1(4330,-210) 4315.24,-224.76 4315.24,-300.24 4340,-325 U1_9.5
NetR3_10_2: R3_10.2 U1_10.5 | length 435.2
  Top Layer w10: R3_10.2 4665,-215 4675,-225 4825,-225 v1(4840,-210)
  Bottom Layer w10: v1(4840,-210) 4825.24,-224.76 4825.24,-300.24 4850,-325 U1_10.5
NetR4_1_2: R4_1.2 U1_1.4 | length 338.4
  Top Layer w10: R4_1.2 60,-335 120,-275 v1(265,-275)
  Bottom Layer w10: v1(265,-275) U1_1.4
NetR4_2_2: R4_2.2 U1_2.4 | length 338.4
  Top Layer w10: R4_2.2 570,-335 630,-275 v1(775,-275)
  Bottom Layer w10: v1(775,-275) U1_2.4
NetR4_3_2: R4_3.2 U1_3.4 | length 338.4
  Top Layer w10: R4_3.2 1080,-335 1140,-275 v1(1285,-275)
  Bottom Layer w10: v1(1285,-275) U1_3.4
NetR4_4_2: R4_4.2 U1_4.4 | length 338.4
  Top Layer w10: R4_4.2 1590,-335 1650,-275 v1(1795,-275)
  Bottom Layer w10: v1(1795,-275) U1_4.4
NetR4_5_2: R4_5.2 U1_5.4 | length 338.4
  Top Layer w10: R4_5.2 2100,-335 2160,-275 v1(2305,-275)
  Bottom Layer w10: v1(2305,-275) U1_5.4
NetR4_6_2: R4_6.2 U1_6.4 | length 338.4
  Top Layer w10: R4_6.2 2610,-335 2670,-275 v1(2815,-275)
  Bottom Layer w10: v1(2815,-275) U1_6.4
NetR4_7_2: R4_7.2 U1_7.4 | length 338.4
  Top Layer w10: R4_7.2 3120,-335 3180,-275 v1(3325,-275)
  Bottom Layer w10: v1(3325,-275) U1_7.4
NetR4_8_2: R4_8.2 U1_8.4 | length 338.4
  Top Layer w10: R4_8.2 3630,-335 3690,-275 v1(3835,-275)
  Bottom Layer w10: v1(3835,-275) U1_8.4
NetR4_9_2: R4_9.2 U1_9.4 | length 338.4
  Top Layer w10: R4_9.2 4140,-335 4200,-275 v1(4345,-275)
  Bottom Layer w10: v1(4345,-275) U1_9.4
NetR4_10_2: R4_10.2 U1_10.4 | length 338.4
  Top Layer w10: R4_10.2 4650,-335 4710,-275 v1(4855,-275)
  Bottom Layer w10: v1(4855,-275) U1_10.4
NetR5_1_2: R5_1.2 U1_1.3 | length 511.4
  Top Layer w10: R5_1.2 125,-389.65 125,-322.91 152.91,-295 175,-295 181,-301 v1(389,-301)
  Bottom Layer w10: U1_1.3 353,-225 389,-261 v1(389,-301)
NetR5_2_2: R5_2.2 U1_2.3 | length 511.4
  Top Layer w10: R5_2.2 635,-389.65 635,-322.91 662.91,-295 685,-295 691,-301 v1(899,-301)
  Bottom Layer w10: U1_2.3 863,-225 899,-261 v1(899,-301)
NetR5_3_2: R5_3.2 U1_3.3 | length 511.4
  Top Layer w10: R5_3.2 1145,-389.65 1145,-322.91 1172.91,-295 1195,-295 1201,-301 v1(1409,-301)
  Bottom Layer w10: U1_3.3 1373,-225 1409,-261 v1(1409,-301)
NetR5_4_2: R5_4.2 U1_4.3 | length 511.4
  Top Layer w10: R5_4.2 1655,-389.65 1655,-322.91 1682.91,-295 1705,-295 1711,-301 v1(1919,-301)
  Bottom Layer w10: U1_4.3 1883,-225 1919,-261 v1(1919,-301)
NetR5_5_2: R5_5.2 U1_5.3 | length 511.4
  Top Layer w10: R5_5.2 2165,-389.64 2165,-322.91 2192.91,-295 2215,-295 2221,-301 v1(2429,-301)
  Bottom Layer w10: U1_5.3 2393,-225 2429,-261 v1(2429,-301)
NetR5_6_2: R5_6.2 U1_6.3 | length 511.4
  Top Layer w10: R5_6.2 2675,-389.64 2675,-322.91 2702.91,-295 2725,-295 2731,-301 v1(2939,-301)
  Bottom Layer w10: U1_6.3 2903,-225 2939,-261 v1(2939,-301)
NetR5_7_2: R5_7.2 U1_7.3 | length 511.4
  Top Layer w10: R5_7.2 3185,-389.64 3185,-322.91 3212.91,-295 3235,-295 3241,-301 v1(3449,-301)
  Bottom Layer w10: U1_7.3 3413,-225 3449,-261 v1(3449,-301)
NetR5_8_2: R5_8.2 U1_8.3 | length 511.4
  Top Layer w10: R5_8.2 3695,-389.64 3695,-322.91 3722.91,-295 3745,-295 3751,-301 v1(3959,-301)
  Bottom Layer w10: U1_8.3 3923,-225 3959,-261 v1(3959,-301)
NetR5_9_2: R5_9.2 U1_9.3 | length 511.4
  Top Layer w10: R5_9.2 4205,-389.64 4205,-322.91 4232.91,-295 4255,-295 4261,-301 v1(4469,-301)
  Bottom Layer w10: U1_9.3 4433,-225 4469,-261 v1(4469,-301)
NetR5_10_2: R5_10.2 U1_10.3 | length 511.4
  Top Layer w10: R5_10.2 4715,-389.64 4715,-322.91 4742.91,-295 4765,-295 4771,-301 v1(4979,-301)
  Bottom Layer w10: U1_10.3 4943,-225 4979,-261 v1(4979,-301)
NetR6_1_2: R6_1.2 U1_1.2 | length 362
  Top Layer w10: v3(250,-415) R6_1.2
  Bottom Layer w10: v3(250,-415) 215,-380 215,-195 235,-175 U1_1.2
NetR6_2_2: R6_2.2 U1_2.2 | length 362
  Top Layer w10: v3(760,-415) R6_2.2
  Bottom Layer w10: v3(760,-415) 725,-380 725,-195 745,-175 U1_2.2
NetR6_3_2: R6_3.2 U1_3.2 | length 362
  Top Layer w10: v3(1270,-415) R6_3.2
  Bottom Layer w10: v3(1270,-415) 1235,-380 1235,-195 1255,-175 U1_3.2
NetR6_4_2: R6_4.2 U1_4.2 | length 362
  Top Layer w10: v3(1780,-415) R6_4.2
  Bottom Layer w10: v3(1780,-415) 1745,-380 1745,-195 1765,-175 U1_4.2
NetR6_5_2: R6_5.2 U1_5.2 | length 362
  Top Layer w10: v3(2290,-415) R6_5.2
  Bottom Layer w10: v3(2290,-415) 2255,-380 2255,-195 2275,-175 U1_5.2
NetR6_6_2: R6_6.2 U1_6.2 | length 362
  Top Layer w10: v3(2800,-415) R6_6.2
  Bottom Layer w10: v3(2800,-415) 2765,-380 2765,-195 2785,-175 U1_6.2
NetR6_7_2: R6_7.2 U1_7.2 | length 362
  Top Layer w10: v3(3310,-415) R6_7.2
  Bottom Layer w10: v3(3310,-415) 3275,-380 3275,-195 3295,-175 U1_7.2
NetR6_8_2: R6_8.2 U1_8.2 | length 362
  Top Layer w10: v3(3820,-415) R6_8.2
  Bottom Layer w10: v3(3820,-415) 3785,-380 3785,-195 3805,-175 U1_8.2
NetR6_9_2: R6_9.2 U1_9.2 | length 362
  Top Layer w10: v3(4330,-415) R6_9.2
  Bottom Layer w10: v3(4330,-415) 4295,-380 4295,-195 4315,-175 U1_9.2
NetR6_10_2: R6_10.2 U1_10.2 | length 362
  Top Layer w10: v3(4840,-415) R6_10.2
  Bottom Layer w10: v3(4840,-415) 4805,-380 4805,-195 4825,-175 U1_10.2
NetR7_1_2: R7_1.2 U1_1.1 | length 155.9
  Top Layer w10: v1(255,-125) 285,-95 R7_1.2
  Bottom Layer w10: v1(255,-125) U1_1.1
NetR7_2_2: R7_2.2 U1_2.1 | length 155.9
  Top Layer w10: v1(765,-125) 795,-95 R7_2.2
  Bottom Layer w10: v1(765,-125) U1_2.1
NetR7_3_2: R7_3.2 U1_3.1 | length 155.9
  Top Layer w10: v1(1275,-125) 1305,-95 R7_3.2
  Bottom Layer w10: v1(1275,-125) U1_3.1
NetR7_4_2: R7_4.2 U1_4.1 | length 155.9
  Top Layer w10: v1(1785,-125) 1815,-95 R7_4.2
  Bottom Layer w10: v1(1785,-125) U1_4.1
NetR7_5_2: R7_5.2 U1_5.1 | length 155.9
  Top Layer w10: v1(2295,-125) 2325,-95 R7_5.2
  Bottom Layer w10: v1(2295,-125) U1_5.1
NetR7_6_2: R7_6.2 U1_6.1 | length 155.9
  Top Layer w10: v1(2805,-125) 2835,-95 R7_6.2
  Bottom Layer w10: v1(2805,-125) U1_6.1
NetR7_7_2: R7_7.2 U1_7.1 | length 155.9
  Top Layer w10: v1(3315,-125) 3345,-95 R7_7.2
  Bottom Layer w10: v1(3315,-125) U1_7.1
NetR7_8_2: R7_8.2 U1_8.1 | length 155.9
  Top Layer w10: v1(3825,-125) 3855,-95 R7_8.2
  Bottom Layer w10: v1(3825,-125) U1_8.1
NetR7_9_2: R7_9.2 U1_9.1 | length 155.9
  Top Layer w10: v1(4335,-125) 4365,-95 R7_9.2
  Bottom Layer w10: v1(4335,-125) U1_9.1
NetR7_10_2: R7_10.2 U1_10.1 | length 155.9
  Top Layer w10: v1(4845,-125) 4875,-95 R7_10.2
  Bottom Layer w10: v1(4845,-125) U1_10.1
NetR8_1_2: R8_1.2 U1_1.15 | length 88.9
  Bottom Layer w10: U1_1.15 v3(155,-175)
NetR8_2_2: R8_2.2 U1_2.15 | length 88.9
  Bottom Layer w10: U1_2.15 v3(665,-175)
NetR8_3_2: R8_3.2 U1_3.15 | length 88.9
  Bottom Layer w10: U1_3.15 v3(1175,-175)
NetR8_4_2: R8_4.2 U1_4.15 | length 88.9
  Bottom Layer w10: U1_4.15 v3(1685,-175)
NetR8_5_2: R8_5.2 U1_5.15 | length 88.9
  Bottom Layer w10: U1_5.15 v3(2195,-175)
NetR8_6_2: R8_6.2 U1_6.15 | length 88.9
  Bottom Layer w10: U1_6.15 v3(2705,-175)
NetR8_7_2: R8_7.2 U1_7.15 | length 88.9
  Bottom Layer w10: U1_7.15 v3(3215,-175)
NetR8_8_2: R8_8.2 U1_8.15 | length 88.9
  Bottom Layer w10: U1_8.15 v3(3725,-175)
NetR8_9_2: R8_9.2 U1_9.15 | length 88.9
  Bottom Layer w10: U1_9.15 v3(4235,-175)
NetR8_10_2: R8_10.2 U1_10.15 | length 88.9
  Bottom Layer w10: U1_10.15 v3(4745,-175)
NetU1_1_9: pad.9@489.06,-225 U1_1.9 U1_2.14 | length 745.1
  Bottom Layer w10: U1_1.9 245,-475 280,-510 375,-510 432,-453 432,-278 485,-225 U1_2.14
NetU1_1_14: pad.9@-20.94,-225 U1_1.14 | length 91.1
  Bottom Layer w10: pad.9@-25,-225 U1_1.14
NetU1_2_9: pad.9@999.06,-225 U1_2.9 U1_3.14 | length 745.1
  Bottom Layer w10: U1_2.9 755,-475 790,-510 885,-510 942,-453 942,-278 995,-225 999.06,-225 U1_3.14
NetU1_3_9: pad.9@1509.06,-225 U1_3.9 U1_4.14 | length 745.1
  Bottom Layer w10: U1_3.9 1265,-475 1300,-510 1395,-510 1452,-453 1452,-278 1505,-225 U1_4.14
NetU1_4_9: pad.9@2019.06,-225 U1_4.9 U1_5.14 | length 745.1
  Bottom Layer w10: U1_4.9 1775,-475 1810,-510 1905,-510 1962,-453 1962,-278 2015,-225 U1_5.14
NetU1_5_9: pad.9@2529.06,-225 U1_5.9 U1_6.14 | length 745.1
  Bottom Layer w10: U1_5.9 2285,-475 2320,-510 2415,-510 2472,-453 2472,-278 2525,-225 U1_6.14
NetU1_6_9: pad.9@3039.06,-225 U1_6.9 U1_7.14 | length 745.1
  Bottom Layer w10: U1_6.9 2795,-475 2830,-510 2925,-510 2982,-453 2982,-278 3035,-225 U1_7.14
NetU1_7_9: pad.9@3549.06,-225 U1_7.9 U1_8.14 | length 745.1
  Bottom Layer w10: U1_7.9 3305,-475 3340,-510 3435,-510 3492,-453 3492,-278 3545,-225 U1_8.14
NetU1_8_9: pad.9@4059.06,-225 U1_8.9 U1_9.14 | length 745.1
  Bottom Layer w10: U1_8.9 3815,-475 3850,-510 3945,-510 4002,-453 4002,-278 4055,-225 U1_9.14
NetU1_9_9: pad.9@4569.06,-225 U1_9.9 U1_10.14 | length 745.1
  Bottom Layer w10: U1_9.9 4325,-475 4360,-510 4455,-510 4512,-453 4512,-278 4565,-225 U1_10.14
NetU1_10_9: U1_10.9
SHCP: pad.11 U1_1.11 U1_2.11 U1_3.11 U1_4.11 U1_5.11 U1_6.11 U1_7.11 U1_8.11 U1_9.11 U1_10.11 | length 5064.1
  Top Layer w10: v2(165,-375) 180,-360 485,-360 v2(507,-382) ; v2(675,-375) 690,-360 995,-360 v2(1017,-382) ; v2(1185,-375) 1200,-360 1505,-360 v2(1527,-382) ; v2(1695,-375) 1710,-360 2015,-360 v2(2037,-382) ; v2(2205,-375) 2220,-360 2525,-360 v2(2547,-382) ; v2(2715,-375) 2730,-360 3035,-360 v2(3057,-382) ; v2(3225,-375) 3240,-360 3545,-360 v2(3567,-382) ; v2(3735,-375) 3750,-360 4055,-360 v2(4077,-382) ; v2(4245,-375) 4260,-360 4565,-360 v2(4587,-382)
  Bottom Layer w10: pad.11@-21,-396 0,-375 U1_1.11 v2(165,-375) ; pad.11@489,-396 510,-375 U1_2.11 v2(675,-375) ; pad.11@999,-396 1020,-375 U1_3.11 v2(1185,-375) ; pad.11@1509,-396 1530,-375 U1_4.11 v2(1695,-375) ; pad.11@2019,-396 2040,-375 v2(2205,-375) ; pad.11@2529,-396 2550,-375 v2(2715,-375) ; pad.11@3039,-396 3060,-375 v2(3225,-375) ; pad.11@3549,-396 3570,-375 v2(3735,-375) ; pad.11@4059,-396 4080,-375 v2(4245,-375) ; pad.11@4569,-396 4590,-375 U1_10.11
STCP: pad.10 U1_1.12 U1_2.12 U1_3.12 U1_4.12 U1_5.12 U1_6.12 U1_7.12 U1_8.12 U1_9.12 U1_10.12 | length 4905.5
  Top Layer w10: v2(165,-325) 180,-340 v2@500,-340 ; v2(675,-325) 690,-340 1014,-340 v2(1015,-339) ; v2(1185,-325) 1200,-340 v2@1524,-340 ; v2(1695,-325) 1710,-340 v2@2034,-340 ; v2(2205,-325) 2220,-340 v2@2544,-340 ; v2(2715,-325) 2730,-340 v2@3054,-340 ; v2(3225,-325) 3240,-340 v2@3564,-340 ; v2(3735,-325) 3750,-340 v2@4074,-340 ; v2(4245,-325) 4260,-340 v2@4584,-340
  Bottom Layer w10: pad.10@-25,-325 U1_1.12 v2(165,-325) ; pad.10@485,-325 U1_2.12 v2(675,-325) ; pad.10@995,-325 999.06,-325 U1_3.12 v2(1185,-325) ; pad.10@1505,-325 U1_4.12 v2(1695,-325) ; pad.10@2015,-325 v2(2205,-325) ; pad.10@2525,-325 v2(2715,-325) ; pad.10@3035,-325 v2(3225,-325) ; pad.10@3545,-325 v2(3735,-325) ; pad.10@4055,-325 v2(4245,-325) ; pad.10@4565,-325 U1_10.12
  other v2: 505,-339 1525,-339 2035,-339 2545,-339 3055,-339 3565,-339 4075,-339 4585,-339

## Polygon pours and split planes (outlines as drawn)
GND on Bottom Layer "Bottom Layer-No Net" (solid, pour order 0): -26,-52 4990,-52 4990,-535 -26,-535
GND on Top Layer "Bottom Layer-No Net" (solid, pour order 4): -26,-52 4990,-52 4990,-535 -26,-535

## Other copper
Bottom Layer:
  pour cut-out: 4914.69,-65.44 ccw(c4924.69,-65.44) 4924.69,-75.44 ccw(c4924.69,-65.44) 4934.69,-65.44 ccw(c4924.69,-65.44) 4924.69,-55.44 ccw(c4924.69,-65.44)
  pour cut-out: 4404.69,-65.44 ccw(c4414.69,-65.44) 4414.69,-75.44 ccw(c4414.69,-65.44) 4424.69,-65.44 ccw(c4414.69,-65.44) 4414.69,-55.44 ccw(c4414.69,-65.44)
  pour cut-out: 3894.69,-65.44 ccw(c3904.69,-65.44) 3904.69,-75.44 ccw(c3904.69,-65.44) 3914.69,-65.44 ccw(c3904.69,-65.44) 3904.69,-55.44 ccw(c3904.69,-65.44)
  pour cut-out: 3384.69,-65.44 ccw(c3394.69,-65.44) 3394.69,-75.44 ccw(c3394.69,-65.44) 3404.69,-65.44 ccw(c3394.69,-65.44) 3394.69,-55.44 ccw(c3394.69,-65.44)
  pour cut-out: 2874.69,-65.44 ccw(c2884.69,-65.44) 2884.69,-75.44 ccw(c2884.69,-65.44) 2894.69,-65.44 ccw(c2884.69,-65.44) 2884.69,-55.44 ccw(c2884.69,-65.44)
  pour cut-out: 2364.69,-65.44 ccw(c2374.69,-65.44) 2374.69,-75.44 ccw(c2374.69,-65.44) 2384.69,-65.44 ccw(c2374.69,-65.44) 2374.69,-55.44 ccw(c2374.69,-65.44)
  pour cut-out: 1854.69,-65.44 ccw(c1864.69,-65.44) 1864.69,-75.44 ccw(c1864.69,-65.44) 1874.69,-65.44 ccw(c1864.69,-65.44) 1864.69,-55.44 ccw(c1864.69,-65.44)
  pour cut-out: 1344.68,-65.44 ccw(c1354.68,-65.44) 1354.68,-75.44 ccw(c1354.68,-65.44) 1364.68,-65.44 ccw(c1354.68,-65.44) 1354.68,-55.44 ccw(c1354.68,-65.44)
  pour cut-out: 834.69,-65.44 ccw(c844.69,-65.44) 844.69,-75.44 ccw(c844.69,-65.44) 854.69,-65.44 ccw(c844.69,-65.44) 844.69,-55.44 ccw(c844.69,-65.44)
  pour cut-out: 324.69,-65.44 ccw(c334.69,-65.44) 334.69,-75.44 ccw(c334.69,-65.44) 344.69,-65.44 ccw(c334.69,-65.44) 334.69,-55.44 ccw(c334.69,-65.44)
